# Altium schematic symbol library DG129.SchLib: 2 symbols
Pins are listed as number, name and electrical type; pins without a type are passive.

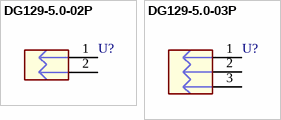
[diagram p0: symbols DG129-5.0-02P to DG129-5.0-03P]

## DG129-5.0-02P
designator U?  (value not drawn)
DG129-5.0-02P-14-00A(H)
footprint DG129-5.0-02P
pins: 1, 2

## DG129-5.0-03P
designator U?  (value not drawn)
DG129-5.0-03P-14-00AH
footprint DG129-5.0-03P (Footprint not found)
pins: 1, 2, 3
